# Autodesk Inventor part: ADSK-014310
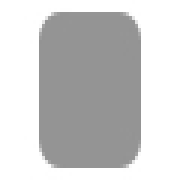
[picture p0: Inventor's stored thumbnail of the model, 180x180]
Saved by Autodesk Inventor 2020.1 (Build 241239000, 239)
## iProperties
Created: 2019-01
Part Number: ADSK-014310
Material: Stahl, weich
Document SubType Name: Modeling
Designer: lutzd
Language: de-DE
Size Designation: 5 x 39,384472 x 39,384472
Categories: <MemberInstance><Categories><Category DisplayName="Sonstige Bauteile" InternalName="5aa15e00-363f-49f2-933f-16f664388e3f" Mnemonic="OTHER"><Category DisplayName
Mass: 60.0398 g
Surface Area: 38.0412 cm^2
Volume: 7.64838 cm^3
Density: 7.85 g/cm^3
Appearance: Semi-Polished(8)
Title: end cap
Author: lutzd
Revision Number: -
DocNumber: ADSK-014310
Folder: 01 - Themengebiete\Simplification\01 - Packaging machine\
VDS_Category: 3D Komponenten
VDS_NumSchm: Autodesk
Dimensions: 39,4x39,4x5 mm
Mass: 0,06 kg
IsCustomPart: 1
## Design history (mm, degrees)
sketch "Sketch1"
  geometry: L1 (0, 20.175)-(0, -21.446); L2 (-20.203, 0)-(20.169, 0); L3 (-19.692, 19.692)-(19.692, 19.692); L4 (19.692, 19.692)-(19.692, -19.692); L5 (19.692, -19.692)-(-19.692, -19.692); L6 (-19.692, -19.692)-(-19.692, 19.692); 1 further point
  constraints: 12 end point, 2 horizontal, 2 parallel, 2 point on line, 1 perpendicular, 1 vertical
  dimensions: "d0" = 39.38447 distance between parallel lines of L5 L3 (= height); "d1" = 19.69224 distance between parallel lines of L2 L3 (= 0.5 x height); "d2" = 39.38447 distance between parallel lines of L6 L4 (= width); "d3" = 19.69224 distance between parallel lines of L6 L1 (= 0.5 x width)
extrude "Extrusion1" new body sketch "Sketch1" distance "d4" = 5 (= thickness); taper "d5" = 0 deg
fillet "Fillet1" dims "d6" = 5 (= fillet), "d7" = 0, "fillet" = 5 [user parameter; used in 1 equation term]
chamfer "Chamfer1" distance "d8" = 0 (computed from chamfer); stored, may be unused: second distance "d9" = 2, angle "d10" = 45 deg; dims "d11" = 0, "chamfer" = 0 [user parameter; used in 1 equation term]
body "Solid1"
other parameters: "thickness" = 5 [user parameter; used in 1 equation term], "width" = 39.38447 [user parameter; used in 2 equation terms], "height" = 39.38447 [user parameter; used in 2 equation terms]
